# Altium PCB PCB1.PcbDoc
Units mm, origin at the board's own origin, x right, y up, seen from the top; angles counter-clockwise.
Board outline 68.58 x 33.2 mm, 2 copper layers (Top Layer, Bottom Layer); 35 components, 49 nets, 171 pads, 51 vias.
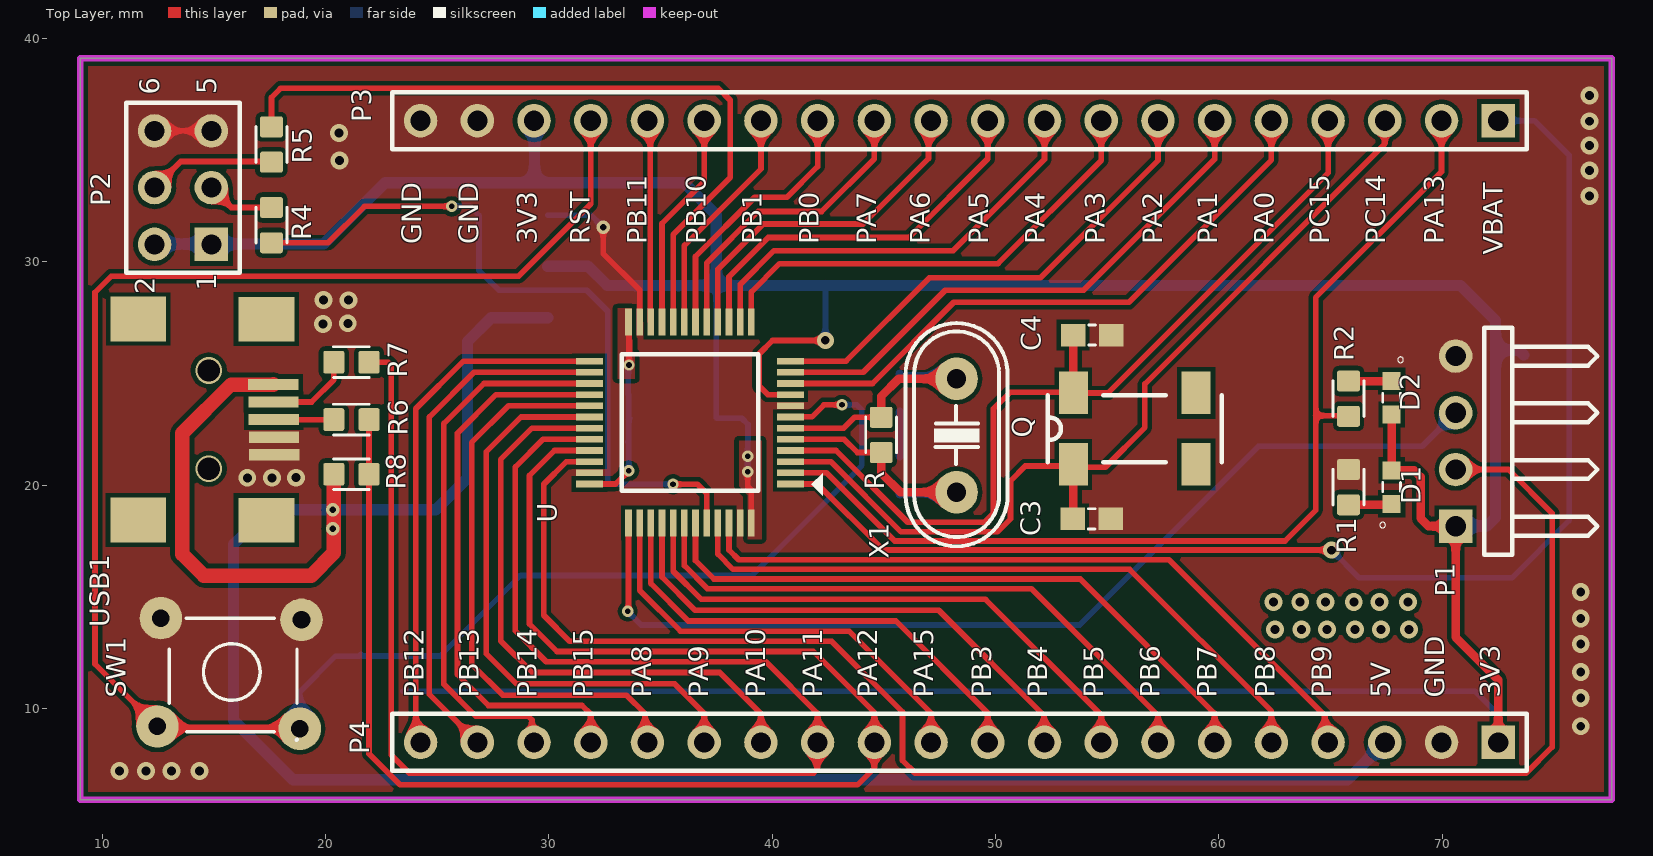
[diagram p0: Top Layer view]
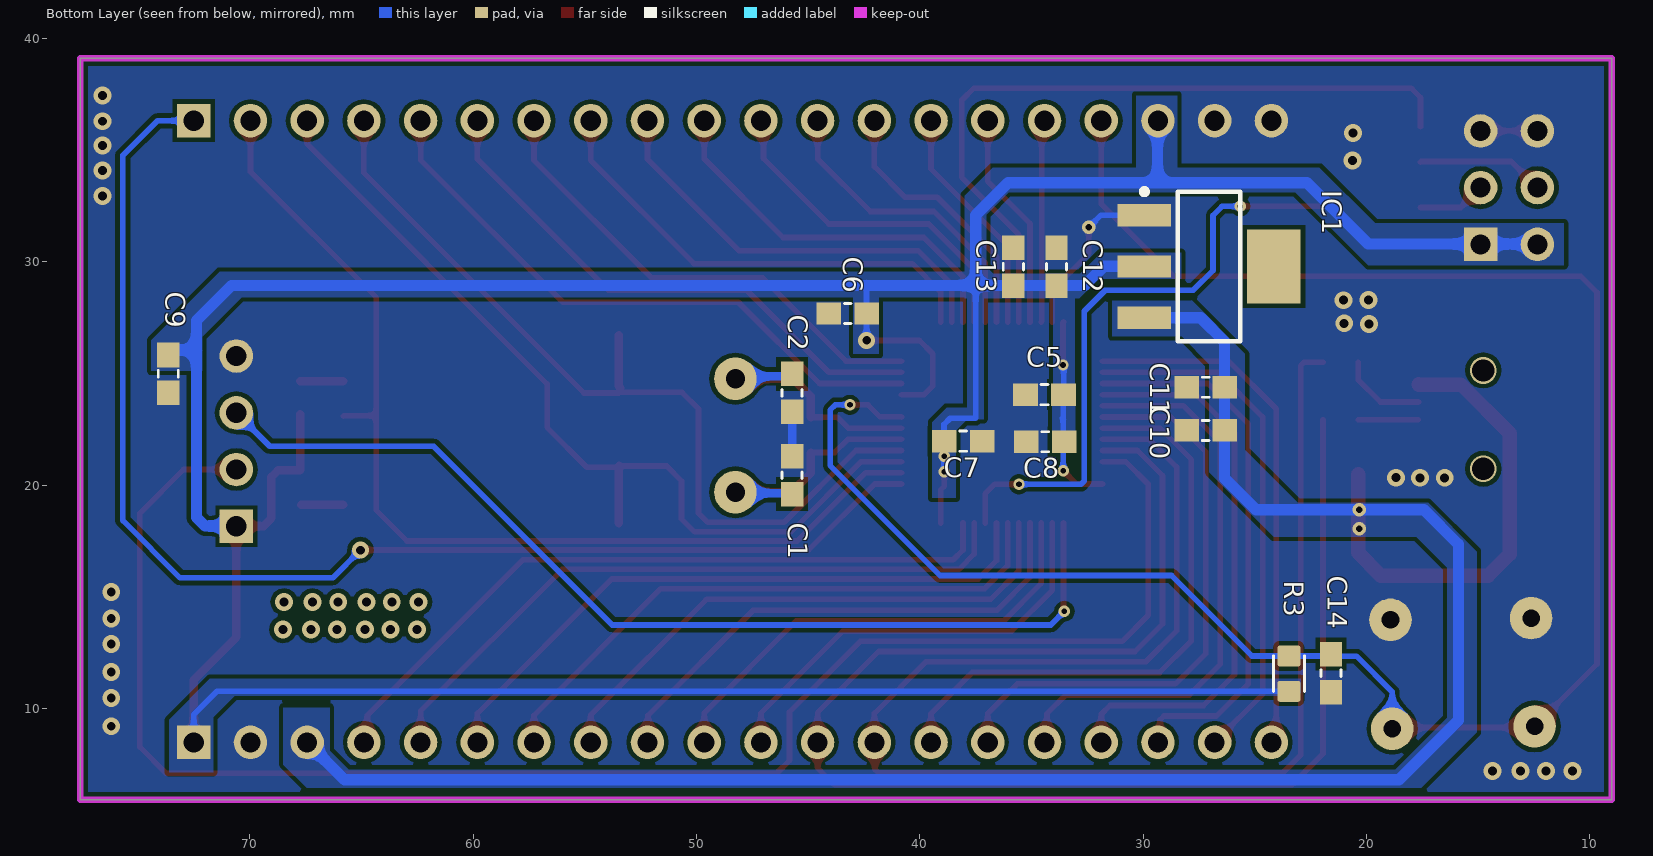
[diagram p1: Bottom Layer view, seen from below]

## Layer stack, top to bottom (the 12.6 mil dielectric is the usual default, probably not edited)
Top Solder: solder mask 0.0102, Solder Resist, Dk 3.5
Top Layer: signal copper 0.0356
Dielectric 1: dielectric 0.32, FR-4, Dk 4.8
Bottom Layer: signal copper 0.0356
Bottom Solder: solder mask 0.0102, Solder Resist, Dk 3.5

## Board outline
9.017,5.918 9.017,39.116 77.597,39.116 77.597,5.918

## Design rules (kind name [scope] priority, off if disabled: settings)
Clearance [All] p1: gap=0.2 ignorepadtopadclearanceinfootprint=FALSE
PolygonConnect [All] p1: connectstyle=Direct reliefconductorwidth=0.254 reliefentries=4 polygonreliefangle="90 Angle" airgapwidth=0.254
RoutingVias [All] p1: holewidth=0.711 width=0.508 viastyle="Through Hole" minholewidth=0.127 minwidth=0.127 maxholewidth=0.711 maxwidth=1.27
SolderMaskExpansion [All] p1: expansion=0.102 istentingtop=FALSE
Width [All] p1: maxlimit=0.762 minlimit=0.254 preferedwidth=0.508
30 further rules are at their usual default settings.

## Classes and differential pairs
net class NewClass: 5V VCC3V3

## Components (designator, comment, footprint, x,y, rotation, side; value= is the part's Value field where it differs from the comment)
C1 "20p,0603" CAPC1608X90 45.72,20.447 r90 bottom
C2 "20p,0603" CAPC1608X90 45.72,24.13 r270 bottom
C3 "20p,0603" CAPC1608X90 54.305,18.491 r0 top
C4 "20p,0603" CAPC1608X90 54.331,26.721 r0 top
C5 "104,0603" CAPC1608X90 34.418,24.055 r0 bottom
C6 "104,0603" CAPC1608X90 43.231,27.686 r0 bottom
C7 "104,0603" CAPC1608X90 38.061,21.971 r180 bottom
C8 "104,0603" CAPC1608X90 34.392,21.946 r0 bottom
C9 "104,0603" CAPC1608X90 73.66,24.98 r270 bottom
C10 "10uF,0603" CAPC1608X90 27.203,22.454 r0 bottom
C11 "0.1uF,0603" CAPC1608X90 27.203,24.384 r0 bottom
C12 "10uF,0603" CAPC1608X90 33.884,29.781 r90 bottom
C13 "0.1uF,0603" CAPC1608X90 35.814,29.781 r90 bottom
C14 "105" CAPC1608X90 21.59,11.582 r270 bottom
D1 "HSMS-C190" LEDM1608X80 67.742,19.914 r90 top
D2 "HSMS-C190" LEDM1608X80 67.742,23.915 r270 top
IC1 "LM1117" SOT223-4N 27.047,29.794 r180 bottom value=LM317
P1 "SWD" HDR1X4H 70.612,18.161 r90 top
P2 "Header 3X2" HDR2X3 14.884,30.785 r90 top
P3 "Header 20" HDR1X20 72.517,36.322 r180 top
P4 "Header 20" HDR1X20 72.517,8.484 r180 top
Q "MC-306" "XT 306" 56.236,22.53 r0 top
R "1M" RESC1608X50N 44.882,22.25 r90 top
R1 "510" RESC1608X50N 65.811,19.911 r270 top
R2 "510" RESC1608X50N 65.811,23.875 r270 top
R3 "10k" RESC1608X50N 23.47,11.56 r90 bottom
R4 "100k" RESC1608X50N 17.577,31.646 r270 top
R5 "100k" RESC1608X50N 17.577,35.255 r270 top
R6 "20" RESC1608X50N 21.158,22.936 r0 top
R7 "20" RESC1608X50N 21.158,25.507 r0 top
R8 "4k7" RESC1608X50N 21.158,20.489 r180 top
SW1 "SW" SW4 12.624,14.046 r0 top value="Button chip 4 pin"
U "STM32F103C8T6" QFP50P900X900X160-48N 36.318,22.805 r180 top
USB1 "USB_M" USB_B_MINI_SMD 17.653,24.511 r90 top
X1 "8Mhz" XT2 48.26,22.225 r270 top value=4Mhz

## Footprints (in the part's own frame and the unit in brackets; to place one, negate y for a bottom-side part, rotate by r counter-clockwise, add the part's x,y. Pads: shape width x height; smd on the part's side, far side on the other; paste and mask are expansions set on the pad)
CAPC1608X90 [mm]
  rect 1.1x1 smd: 1(-0.85,0) 2(0.85,0)
  silkscreen extent -0.15,-0.45 0.15,0.45, body extent -0.81,-0.45 0.79,0.45, height 0.8
HDR1X4H [mm] "Connector; Header; 4 Position; Right Angle"
  rect 1.5x1.5 hole 0.9: 1(0,0)
  round 1.5 hole 0.9: 2(2.54,0) 3(5.08,0) 4(7.62,0)
  silkscreen extent -1.27,-6.35 8.89,-1.27, body extent -1.27,-7 8.89,1.27, height 4.33
HDR1X20 [mm] "Connector; Header; 20 Position"
  rect 1.5x1.5 hole 0.9: 1(0,0)
  round 1.5 hole 0.9: 2(2.54,0) 3(5.08,0) 4(7.62,0) 5(10.16,0) 6(12.7,0) 7(15.24,0) 8(17.78,0) 9(20.32,0) 10(22.86,0) 11(25.4,0) 12(27.94,0) 13(30.48,0) 14(33.02,0) 15(35.56,0) 16(38.1,0) 17(40.64,0) 18(43.18,0) 19(45.72,0) 20(48.26,0)
  silkscreen extent -1.27,-1.27 49.53,1.27, body extent -1.27,-1.78 49.53,1.78, height 8.14
HDR2X3 [mm] "Connector; Header; 3x2 Position"
  rect 1.5x1.5 hole 0.9: 1(0,0)
  round 1.5 hole 0.9: 2(0,2.54) 3(2.54,0) 4(2.54,2.54) 5(5.08,0) 6(5.08,2.54)
  silkscreen extent -1.27,-1.27 6.35,3.81, body extent -1.27,-1.27 6.35,3.81, height 7
LEDM1608X80 [mm]
  rect 0.8x0.8 smd: A(0.75,0) C(-0.75,0)
  silkscreen extent -1.83,-0.4 0.2,0.53, body extent -0.8,-0.3 0.8,0.3, height 0.99
QFP50P900X900X160-48N [mm] "QFP,0.50mm pitch,square;12 pin X 12 pin,7.00mm X 7.00mm X 1.60mm H body"
  rect 1.2x0.3 smd: 1(-4.5,2.75) 2(-4.5,2.25) 3(-4.5,1.75) 4(-4.5,1.25) 5(-4.5,0.75) 6(-4.5,0.25) 7(-4.5,-0.25) 8(-4.5,-0.75) 9(-4.5,-1.25) 10(-4.5,-1.75) 11(-4.5,-2.25) 12(-4.5,-2.75) 25(4.5,-2.75) 26(4.5,-2.25) 27(4.5,-1.75) 28(4.5,-1.25) 29(4.5,-0.75) 30(4.5,-0.25) 31(4.5,0.25) 32(4.5,0.75) 33(4.5,1.25) 34(4.5,1.75) 35(4.5,2.25) 36(4.5,2.75)
  rect 0.3x1.2 smd: 13(-2.75,-4.5) 14(-2.25,-4.5) 15(-1.75,-4.5) 16(-1.25,-4.5) 17(-0.75,-4.5) 18(-0.25,-4.5) 19(0.25,-4.5) 20(0.75,-4.5) 21(1.25,-4.5) 22(1.75,-4.5) 23(2.25,-4.5) 24(2.75,-4.5) 37(2.75,4.5) 38(2.25,4.5) 39(1.75,4.5) 40(1.25,4.5) 41(0.75,4.5) 42(0.25,4.5) 43(-0.25,4.5) 44(-0.75,4.5) 45(-1.25,4.5) 46(-1.75,4.5) 47(-2.25,4.5) 48(-2.75,4.5)
  silkscreen extent -5.94,-3.05 3.05,3.28, body extent -4.5,-4.5 4.5,4.5, height 1.42
RESC1608X50N [mm]
  rrect20% 0.94x1.02 smd: 1(-0.79,0) 2(0.79,0)
  silkscreen extent -0.8,-0.69 0.8,0.69, body extent -0.8,-0.4 0.8,0.4, height 0.37
SOT223-4N [mm] "SOT223, 4-Leads, Body 6.5x3.5mm, Pitch 2.3mm, Lead Span 7mm, IPC Medium Density"
  rect 2.4x1 smd: 1(-2.9,2.3) 2(-2.9,0) 3(-2.9,-2.3)
  rect 2.4x3.3 smd: 4(2.9,0)
  silkscreen extent -3.03,-3.35 1.4,3.47, body extent -3.39,-3.27 3.5,3.23, height 1.72
SW4 [mil] "SW button 4pin, 250 x250 mil"
  round 75 hole 31: 1(0,0) 2(245,-195) 3(248,-3) 4(-6,-191)
  silkscreen extent 15,-215 240,0, body extent -36,-220 276,24, height 276
USB_B_MINI_SMD [mm]
  rect 2x2.5 smd: 0(-6.075,0.305) 0(-6.071,6.045) 0(2.925,0.305) 0(2.929,6.045)
  rect 0.5x2.25 smd: 1(0,0) 2(-0.787,-0.013) 3(-1.575,-0.025) 4(-2.362,-0.038) 5(-3.15,-0.051)
  body extent -6.92,-0.37 3.78,8.83, height 3.95
XT2 [mil] "Footpin for Crystal 2 pin"
  round 75 hole 34: 1(-100,0) 2(100,0)
  silkscreen extent -198,-90 195,90, body extent -233,-93 213,90, height 138
"XT 306" [mm]
  rect 1.3x1.9 smd: 1(-2.75,-1.6) 2(2.75,-1.6) 3(2.75,1.6) 4(-2.75,1.6)
  silkscreen extent -3.9,-1.5 3.9,1.5, body extent -4,-1.9 4,1.9, height 2.39

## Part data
C1 C2 C3 C4 C5 C6 C7 C8 C9 C10 C11 C12 C13 C14: library part CC0603MRX7R9BB272, "CAP CER 2700PF 50V X7R 0603", Package=None
D1 D2: "Red 626nm LED Indication - Discrete 2.1V 0603 _1608 Metric_", Package="0603 Broadcom"
IC1: "3v3"
P1: library part "Header 4H", "Header, 4-Pin, Right Angle"
P2: "Header, 3-Pin, Dual row"
P3 P4: "Header, 20-Pin"
Q: "32.768kHz Â±100ppm Crystal 12.5pF 50 kOhms 4-SOJ, 5.50mm pitch", Package="4-4 Aigner"
R R1 R2 R3 R4 R5 R6 R7 R8: library part 2176051-4, "RES 0.068 OHM 1% 1/8W 0603", Package=0603, Power_Rating=".125 W", Resistance=.068, Tolerance=1%
SW1: library part SW4, "Switch button 4 pin"
U: "ARMÂ® CortexÂ®-M3 STM32F1 Microcontroller IC 32-Bit 72MHz 64KB _64K x 8_ FLASH", Package="LQFP-48 STMicroelectronics"
X1: library part XT2, "Crystal For all Crystal 2pin."

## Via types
v1: diameter 0.8, hole 0.4, Top Layer to Bottom Layer, tented both sides, 36 vias
v2: diameter 0.508, hole 0.254, Top Layer to Bottom Layer, tented both sides, 8 vias
v3: diameter 0.6, hole 0.3, Top Layer to Bottom Layer, tented both sides, 3 vias
v4: diameter 1.2, hole 1, Top Layer to Bottom Layer, 2 vias
v5: diameter 0.762, hole 0.381, Top Layer to Bottom Layer, tented both sides, 2 vias

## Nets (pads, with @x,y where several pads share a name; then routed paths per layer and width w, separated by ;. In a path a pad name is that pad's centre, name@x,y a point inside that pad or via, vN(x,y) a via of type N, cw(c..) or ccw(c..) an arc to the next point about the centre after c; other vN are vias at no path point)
5V: C10.1 C11.1 IC1.3 P4.3 R8.2 USB1.1 | length 104.6
  Top Layer w0.65: USB1.1 17.649,24.507 15.766,24.507 13.589,22.33 13.589,16.916 14.554,15.951 19.355,15.951 20.368,16.965 R8.2
  Bottom Layer w0.508: IC1.3 27.418,27.494 26.353,26.43 C11.1 C10.1 26.353,20.308 24.943,18.898 17.424,18.898 15.875,17.348 15.875,9.474 18.542,6.807 65.761,6.807 P4.3
  other v3: 20.325,18.044 20.325,18.898
BOOT0: R4.2 U.44 | length 32.7
  Top Layer w0.254: R4.2 20.112,30.856 21.742,32.487 v2(25.654,32.487) ; v2(35.56,20.041) 36.652,20.041 37.068,19.625 U.44
  Bottom Layer w0.254: v2(25.654,32.487) 26.467,32.487 26.873,32.08 26.873,29.616 27.762,28.727 31.699,28.727 32.639,27.788 32.639,20.189 32.788,20.041 v2(35.56,20.041)
BOOT1: R5.1 U.20 | length 33.2
  Top Layer w0.254: R5.1 17.577,37.363 17.983,37.77 37.592,37.77 38.125,37.236 38.125,33.782 35.568,31.225 U.20
GND: C1.2 C2.2 C3.2 C4.2 C5.2 C6.2 C7.2 C8.2 C9.2 C10.2 C11.2 C12.2 C13.2 C14.2 IC1.1 P1.4 P2.5 P2.6 P3.19 P3.20 P4.2 R1.1 SW1.1 SW1.3 U.8 U.23 U.35 U.47 USB1.4 USB1.5 | length 12.2
  Top Layer w0.254: P2.6 P2.5 ; v3(32.431,31.547) 32.431,30.381 34.068,28.744 U.23
  Bottom Layer w0.254: IC1.1 31.883,32.094 v3(32.431,31.547)
  Bottom Layer w0.381: C1.2 C2.2
  other v1: 10.765,7.198 11.956,7.198 13.094,7.198 14.356,7.198 76.213,9.205 76.213,10.467 76.213,11.626 76.213,12.888 76.213,14.026 76.213,15.217 16.495,20.33 17.6,20.33 18.684,20.335 19.891,27.221 20.996,27.249 19.906,28.296 21.024,28.283 76.599,32.949 76.599,34.084 20.617,34.539 76.599,35.204 20.604,35.768 76.599,36.297 76.599,37.445
NetD1_C: D1.C R1.2 | length 1.9
  Top Layer w0.254: D1.C@67.699,19.121 D1.C
  Top Layer w0.381: R1.2 D1.C@67.699,19.121
NetD2_C: D2.C R2.1 | length 1.9
  Top Layer w0.381: R2.1 D2.C
NetP2_3: P2.3 R4.1 | length 3.1
  Top Layer w0.254: P2.3 15.773,32.436 R4.1
NetP2_4: P2.4 R5.2 | length 5.7
  Top Layer w0.254: P2.4 13.513,34.493 17.549,34.493 R5.2
NetR6_1: R6.1 USB1.3 | length 2.7
  Top Layer w0.254: USB1.3 R6.1
NetR7_1: R7.1 USB1.2 | length 3.9
  Top Layer w0.254: USB1.2 19.375,23.724 20.368,24.717 R7.1
NRST: C14.1 P3.17 R3.2 SW1.2 SW1.4 U.7 | length 91.7
  Top Layer w0.254: SW1.2 18.796,9.144 14.326,9.144 12.522,9.144 SW1.4 9.677,11.989 9.677,28.633 10.406,29.362 28.651,29.362 31.877,32.588 P3.17 ; U.7 40.822,23.059 41.779,23.059 42.316,23.597 v2(43.129,23.597)
  Bottom Layer w0.254: SW1.2 18.847,10.744 20.447,12.344 21.502,12.344 C14.1 21.673,12.35 R3.2 25.126,12.35 28.727,15.951 39.091,15.951 44.018,20.879 44.018,23.368 43.79,23.597 v2(43.129,23.597)
OSC_IN: C1.1 R.1 U.5 X1.2 | length 11.5
  Top Layer w0.254: U.5 43.223,22.055 43.818,21.46 R.1
  Top Layer w0.381: R.1 44.882,20.549 45.745,19.685 X1.2
  Bottom Layer w0.381: C1.1 45.764,19.641 48.216,19.641 X1.2
OSC_OUT: C2.1 R.2 U.6 X1.1 | length 11.5
  Top Layer w0.254: U.6 43.205,22.555 43.691,23.04 R.2
  Top Layer w0.381: R.2 44.882,23.978 45.669,24.765 X1.1
  Bottom Layer w0.381: C2.1 45.828,24.873 48.152,24.873 X1.1
PA0: P3.5 U.10 | length 27.4
  Top Layer w0.254: U.10 44.494,24.555 48.133,28.194 55.982,28.194 62.357,34.569 P3.5
PA1: P3.6 U.11 | length 24.7
  Top Layer w0.254: U.11 44.08,25.055 47.752,28.727 53.95,28.727 59.817,34.595 P3.6
PA2: P3.7 U.12 | length 22
  Top Layer w0.254: U.12 43.31,25.555 47.041,29.286 52.019,29.286 57.277,34.544 P3.7
PA3: P3.8 U.13 | length 21.2
  Top Layer w0.254: U.13 39.068,28.654 40.335,29.921 50.114,29.921 54.737,34.544 P3.8
PA4: P3.9 U.14 | length 19.4
  Top Layer w0.254: U.14 38.568,28.992 40.081,30.505 48.108,30.505 52.197,34.595 P3.9
PA5: P3.10 U.15 | length 17.5
  Top Layer w0.254: U.15 38.068,29.33 39.827,31.09 46.126,31.09 49.657,34.62 P3.10
PA6: P3.11 U.16 | length 15.6
  Top Layer w0.254: U.16 37.568,29.669 39.599,31.699 44.069,31.699 47.002,34.632 47.002,36.207 P3.11
PA7: P3.12 U.17 | length 13.8
  Top Layer w0.254: U.17 37.068,29.952 39.374,32.258 42.215,32.258 44.577,34.62 P3.12
PA8: P4.16 U.29 | length 25.9
  Top Layer w0.254: U.29 28.19,23.555 26.543,21.907 26.543,11.989 27.94,10.592 33.477,10.592 34.302,9.767 34.302,8.599 P4.16
PA9: P4.15 U.30 | length 26.5
  Top Layer w0.254: U.30 28.757,23.055 27.203,21.501 27.203,12.446 28.55,11.1 35.636,11.1 36.957,9.779 P4.15
PA10: P4.14 U.31 | length 27
  Top Layer w0.254: U.31 29.248,22.555 27.838,21.145 27.838,13.03 29.261,11.608 37.655,11.608 39.497,9.766 P4.14
PA11: P4.13 R7.2 U.32 | length 66.7
  Top Layer w0.254: R7.2 22.8,25.507 22.949,25.358 22.949,11.384 22.936,11.372 22.936,7.925 23.749,7.112 41.859,7.112 42.012,7.264 42.012,8.458 P4.13 42.037,9.779 39.726,12.09 29.883,12.09 28.499,13.475 28.499,20.815 29.738,22.055 U.32
PA12: P4.12 R6.2 R8.1 U.33 | length 67.8
  Top Layer w0.254: R6.2 R8.1 21.948,7.973 23.343,6.579 43.815,6.579 44.577,7.341 P4.12 44.577,9.817 41.847,12.548 30.367,12.548 29.134,13.781 29.134,20.434 30.252,21.553 31.816,21.553 U.33
PA15: P4.11 U.38 | length 19.7
  Top Layer w0.254: U.38 34.068,15.284 35.89,13.462 43.447,13.462 47.117,9.792 P4.11
PB0: P3.13 U.18 | length 12.1
  Top Layer w0.254: U.18 36.568,30.243 39.218,32.893 40.665,32.893 42.037,34.265 P3.13
PB1: P3.14 U.19 | length 10.4
  Top Layer w0.254: U.19 36.068,30.734 39.497,34.163 P3.14
PB3: P4.10 U.39 | length 21.5
  Top Layer w0.254: U.39 34.568,15.597 36.246,13.919 45.542,13.919 49.657,9.804 P4.10
PB4: P4.9 U.40 | length 23.3
  Top Layer w0.254: U.40 35.068,15.884 36.551,14.402 47.46,14.402 52.171,9.691 52.171,8.51 P4.9
PB5: P4.8 U.41 | length 25.2
  Top Layer w0.254: U.41 35.568,16.146 36.83,14.884 49.555,14.884 54.737,9.703 P4.8
PB6: P4.7 U.42 | length 27.1
  Top Layer w0.254: U.42 36.068,16.396 37.097,15.367 51.6,15.367 57.276,9.691 P4.7
PB7: P4.6 U.43 | length 29.1
  Top Layer w0.254: U.43 36.568,16.62 37.389,15.799 53.797,15.799 59.817,9.779 P4.6
PB8: P4.5 U.45 | length 30.5
  Top Layer w0.254: U.45 37.568,16.915 38.252,16.231 56.007,16.231 62.357,9.881 P4.5
PB9: P4.4 U.46 | length 32.2
  Top Layer w0.254: U.46 38.07,18.303 38.07,17.098 38.506,16.662 57.772,16.662 64.744,9.691 64.744,8.637 P4.4
PB10: P3.15 U.21 | length 9.8
  Top Layer w0.254: U.21 35.068,31.715 36.957,33.604 P3.15
PB11: P3.16 U.22 | length 9.1
  Top Layer w0.254: P3.16 34.545,36.194 34.545,27.328 U.22
PB12: P4.20 U.25 | length 23.7
  Top Layer w0.254: P4.20 24.041,8.7 24.041,23.419 26.177,25.555 U.25
PB13: P4.19 U.26 | length 23.5
  Top Layer w0.254: P4.19 24.651,10.63 24.651,23.05 26.655,25.055 U.26
PB14: P4.18 U.27 | length 24.6
  Top Layer w0.254: P4.18 29.242,8.579 29.242,9.486 29.063,9.665 26.721,9.665 25.298,11.087 25.298,22.758 27.095,24.555 U.27
PB15: P4.17 U.28 | length 25.4
  Top Layer w0.254: U.28 27.636,24.055 25.908,22.327 25.908,11.519 27.292,10.135 31.483,10.135 31.877,9.741 P4.17
PC13: P3.2 R2.2 U.2 | length 46.6
  Top Layer w0.254: U.2 42.437,20.555 45.491,17.501 62.967,17.501 64.338,18.872 64.338,23.114 ; R2.2 65.782,23.114 64.338,23.114 ; P3.2 69.977,34.036 64.338,28.397 64.338,23.114
PC14: C3.1 P3.3 Q.1 U.3 | length 41
  Top Layer w0.254: U.3 42.623,21.055 45.771,17.907 50.089,17.907 50.673,18.491 50.673,20.193 51.336,20.856 53.412,20.856 Q.1 53.613,20.803 54.915,20.803 56.693,22.581 56.693,24.536 67.437,35.281 P3.3
  Top Layer w0.381: Q.1@53.412,20.856 53.481,20.787 C3.1@53.481,18.305
PC15: C4.1 P3.4 Q.4 U.4 | length 39.4
  Top Layer w0.254: U.4 42.859,21.555 46.076,18.339 49.505,18.339 49.911,18.745 49.911,23.419 50.648,24.155 53.46,24.155 Q.4 55.042,24.13 64.897,33.985 P3.4
  Top Layer w0.381: Q.4@53.412,24.356 53.481,24.425 C4.1
SWDCLK: P1.3 U.37 | length 45.2
  Top Layer w0.254: v2(33.528,14.351) 33.568,14.391 U.37
  Bottom Layer w0.254: v2(33.528,14.351) 34.138,13.741 53.772,13.741 61.773,21.742 69.113,21.742 P1.3
SWDIO: P1.2 U.34 | length 73.8
  Top Layer w0.254: U.34 30.783,21.055 29.769,20.041 29.769,14.173 30.937,13.005 42.672,13.005 45.834,9.843 45.834,7.671 46.406,7.099 73.762,7.099 74.93,8.268 74.93,18.745 72.974,20.701 P1.2
VBAT: P3.1 U.1 | length 57.9
  Top Layer w0.254: U.1 42.023,20.055 44.983,17.094 v5(65.049,17.094)
  Bottom Layer w0.254: v5(65.049,17.094) 66.294,15.85 73.127,15.85 75.692,18.415 75.692,34.773 74.143,36.322 P3.1
VCC3V3: C5.1 C6.1 C7.1 C8.1 C9.1 C12.1 C13.1 D1.A D2.A IC1.2 P1.1 P2.1 P2.2 P3.18 P4.1 R3.1 U.9 U.24 U.36 U.48 | length 186.7
  Top Layer w0.254: U.36 32.984,20.055 v2(33.579,20.65) ; U.24 33.553,27.29 33.591,27.253 v2(33.591,25.383) ; v2@38.911,20.598 38.911,19.941 39.068,19.784 U.48 ; U.9 39.801,24.055 39.421,24.435 39.421,25.883 40.019,26.48 v5(42.381,26.48)
  Top Layer w0.381: D2.A D1.A 68.744,20.664 69.037,20.371 69.037,18.517 69.393,18.161 P1.1 70.612,13.183 72.517,11.278 P4.1
  Bottom Layer w0.254: R3.1 71.476,10.77 72.517,9.728 P4.1 ; v2(33.579,20.65) 33.585,20.656 33.585,21.903 C8.1 33.574,21.978 33.574,22.954 ; v2(33.591,25.383) 33.559,25.351 33.559,24.064 33.574,24.049 33.574,22.954 ; 33.62,23 33.574,22.954 ; 37.496,28.943 37.496,23.025 37.522,23 38.639,23 38.917,22.722 38.917,21.977 38.9,21.96 v2(38.9,21.29) ; v2@38.911,20.598 v2@38.911,21.29 ; 41.662,28.943 41.726,28.879 ; 42.373,28.943 42.387,28.93 42.387,27.692 C6.1 42.387,27.68 42.387,26.486 v5(42.381,26.48)
  Bottom Layer w0.508: P2.2 12.357,30.797 14.872,30.797 P2.1 14.897,30.797 19.919,30.797 22.663,33.541 29.356,33.541 ; P3.18 29.356,36.303 29.356,33.541 ; IC1.2 29.959,29.807 31.756,29.807 32.619,28.943 33.871,28.943 C12.1 33.896,28.943 35.801,28.943 C13.1 35.827,28.943 37.496,28.943 ; P1.1 70.625,18.174 72.015,18.174 72.396,18.555 72.396,26.048 ; C9.1 73.442,26.048 72.396,26.048 ; 29.356,33.541 36.048,33.541 37.496,32.093 37.496,28.943 ; 37.496,28.943 41.662,28.943 42.373,28.943 70.821,28.943 72.396,27.369 72.396,26.048
  other v2: 38.9,20.598
pads on no net: IC1.4 Q.2 Q.3 USB1.0
copper on no net:
  other v1: 62.512,13.533 63.703,13.533 64.841,13.533 66.103,13.533 67.262,13.533 68.524,13.533 62.456,14.773 63.647,14.773 64.785,14.773 66.048,14.773 67.206,14.773 68.468,14.773
  other v4: 14.768,20.736 14.768,25.136

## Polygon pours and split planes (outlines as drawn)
GND on Top Layer "GND_L01_P025" (solid, remove dead copper, pour order 25): 9.017,39.116 77.597,39.116 77.597,5.918 9.017,5.918
VCC3V3 on Top Layer "VCC3V3_L01_P024" (solid, remove dead copper, pour order 24): 33.076,27.925 33.076,24.77 33.851,24.77 33.851,25.908 33.762,25.997 33.762,27.925
VCC3V3 on Top Layer "VCC3V3_L01_P014" (solid, remove dead copper, pour order 14): 38.898,17.582 39.533,17.582 39.533,21.991 38.517,21.991 38.517,19.944 38.903,19.558 38.903,17.564
GND on Top Layer "GND_L01_P001" (solid, remove dead copper, pour order 1): 6.223,38.252
GND on Bottom Layer "GND_L02_P026" (solid, remove dead copper, pour order 26): 9.017,39.116 77.597,39.116 77.597,5.918 9.017,5.918
VCC3V3 on Bottom Layer "VCC3V3_L02_P020" (solid, remove dead copper, pour order 20): 22.949,11.323 71.796,11.323 73.624,9.495 73.624,7.142 71.651,7.142 71.651,9.604 70.686,10.569 22.939,10.569 22.931,10.577
VCC3V3 on Bottom Layer "VCC3V3_L02_P019" (solid, remove dead copper, pour order 19): 37.798,29.563 71.346,29.563 74.417,26.492 74.417,25.116 72.141,25.116 72.141,26.647 70.376,28.412 37.747,28.412
VCC3V3 on Bottom Layer "VCC3V3_L02_P018" (solid, remove dead copper, pour order 18): 33.045,23.538 33.045,21.745 34.077,21.745 34.077,23.995 33.017,23.995 33.017,24.079
VCC3V3 on Bottom Layer "VCC3V3_L02_P017" (solid, remove dead copper, pour order 17): 33.071,28.471 33.071,24.305 34.023,24.305 34.023,28.971 33.05,28.971
VCC3V3 on Bottom Layer "VCC3V3_L02_P016" (solid, remove dead copper, pour order 16): 28.298,30.404 31.882,30.406 32.814,29.474 36.703,29.474 37.036,29.807 37.036,32.111 36.027,33.119 23.183,33.119 19.916,29.853 11.153,29.853 11.153,31.722 19.606,31.722 22.106,34.221 28.466,34.221 28.466,37.445 30.312,37.445 30.312,34.221 36.741,34.221 37.996,32.967 37.996,28.377 32.852,28.377 31.991,29.238 28.298,29.238
VCC3V3 on Bottom Layer "VCC3V3_L02_P015" (solid, remove dead copper, pour order 15): 41.834,28.875 41.834,25.878 42.982,25.878 42.982,28.898
VCC3V3 on Bottom Layer "VCC3V3_L02_P013" (solid, remove dead copper, pour order 13): 37.687,23.472 38.791,23.472 39.449,22.814 39.449,19.439 38.39,19.439 38.39,22.446 37.702,23.133
VCC3V3 on Bottom Layer "VCC3V3_L02_P012" (solid, remove dead copper, pour order 12): 37.142,28.949 37.142,22.959 37.876,22.959 37.876,28.953
5V on Bottom Layer "5V_L02_P011" (solid, remove dead copper, pour order 11): 31.377,28.26 31.377,26.662 28.278,26.662 27.033,25.418 27.033,20.577 24.153,17.696 17.77,17.696 16.378,16.304 16.378,9.591 18.705,7.264 65.585,7.264 66.429,8.108 66.429,10.043 68.509,10.043 68.509,7.49 67.46,6.441 17.546,6.441 15.052,8.936 15.052,17.023 17.239,19.21 21.605,19.21 23.073,19.21 25.441,21.577 25.441,25.885 27.832,28.276
no net on Bottom Layer "NONET_L02_P010" (solid, remove dead copper, pour order 10): 31.018,28.174
5V on Bottom Layer "5V_L02_P007" (solid, remove dead copper, pour order 7): 24.968,29.337
5V on Bottom Layer "5V_L02_P006" (solid, remove dead copper, pour order 6): 24.943,28.245

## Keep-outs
Keep-Out Layer:
  the board outline again, w0.3

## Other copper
Top Layer:
  region: 31.818,23.055

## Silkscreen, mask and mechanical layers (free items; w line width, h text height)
Top Overlay:
  text "GND" at 24.587,30.78 h1.5 r90
  text "GND" at 27.127,30.78 h1.5 r90
  text "3V3" at 29.746,30.78 h1.5 r90
  text "RST" at 32.133,30.78 h1.5 r90
  text "PB11" at 34.684,30.78 h1.5 r90
  text "PB10" at 37.325,30.78 h1.5 r90
  text "PB1" at 39.832,30.78 h1.5 r90
  text "PB0" at 42.382,30.78 h1.5 r90
  text "PA7" at 44.95,30.78 h1.5 r90
  text "PA6" at 47.358,30.78 h1.5 r90
  text "PA5" at 49.972,30.78 h1.5 r90
  text "PA4" at 52.509,30.78 h1.5 r90
  text "PA3" at 55.194,30.78 h1.5 r90
  text "PA2" at 57.755,30.78 h1.5 r90
  text "PA1" at 60.218,30.78 h1.5 r90
  text "PA0" at 62.753,30.78 h1.5 r90
  text "PC15" at 65.237,30.78 h1.5 r90
  text "PC14" at 67.743,30.78 h1.5 r90
  text "PA13" at 70.378,30.78 h1.5 r90
  text "VBAT" at 73.02,30.325 h1.5 r90
  text "PB12" at 24.699,10.488 h1.5 r90
  text "PB13" at 27.16,10.488 h1.5 r90
  text "PB14" at 29.751,10.488 h1.5 r90
  text "PB15" at 32.26,10.488 h1.5 r90
  text "PA8" at 34.874,10.488 h1.5 r90
  text "PA9" at 37.439,10.488 h1.5 r90
  text "PA10" at 39.992,10.488 h1.5 r90
  text "PA11" at 42.525,10.488 h1.5 r90
  text "PA12" at 44.988,10.488 h1.5 r90
  text "PA15" at 47.51,10.488 h1.5 r90
  text "PB3" at 50.099,10.488 h1.5 r90
  text "PB4" at 52.608,10.488 h1.5 r90
  text "PB5" at 55.113,10.488 h1.5 r90
  text "PB6" at 57.653,10.488 h1.5 r90
  text "PB7" at 60.193,10.488 h1.5 r90
  text "PB8" at 62.796,10.488 h1.5 r90
  text "PB9" at 65.318,10.488 h1.5 r90
  text "5V" at 67.97,10.488 h1.5 r90
  text "GND" at 70.381,10.488 h1.5 r90
  text "3V3" at 72.872,10.488 h1.5 r90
